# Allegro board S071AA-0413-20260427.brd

Outline 292.64 x 429.26 mm; copper layers: TOP, L02_DGND, L03_DIG, L04_DGND, L05_DIG, L06_DGND, L07_DIG, L08_DGND, L09_DPS, L10_DGND, L11_DPS, L12_DGND, L13_CBIT, L14_5V, L15_DGND, L16_DPS, L17_DGND, L18_DIG, L19_DGND, L20_DIG, L21_DGND, L22_DIG, L23_DGND, L24_DIG, L25_DGND, BOTTOM. Coordinates in mm from the lower left corner of the outline.

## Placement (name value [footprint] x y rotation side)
BDB4  BD120-3A-S8  [FB0805]  17.8 140.46 180 bottom
BDB5  BD120-3A-S8  [FB0805]  142.51 263.88 180 bottom
BDB6  BD120-3A-S8  [FB0805]  175.3 247.77 180 bottom
BDB7  BD120-3A-S8  [FB0805]  192.18 233.42 180 bottom
BDB8  BD120-3A-S8  [FB0805]  189.46 211.4 180 bottom
BDB9  BD120-3A-S8  [FB0805]  188.62 176.29 180 bottom
BDB10  BD120-3A-S8  [FB0805]  162.21 175.22 180 bottom
BDB13  BD120-3A-S8  [FB0805]  63.77 269.13 180 bottom
BDB14  BD120-3A-S8  [FB0805]  60.72 250.95 180 bottom
BDB15  BD120-3A-S8  [FB0805]  63.77 266.34 180 bottom
BDB16  BD120-3A-S8  [FB0805]  60.72 248.16 180 bottom
BDB17  BD120-3A-S8  [FB0805]  162.21 172.43 180 bottom
BDB18  BD120-3A-S8  [FB0805]  188.62 179.08 180 bottom
BDB19  BD120-3A-S8  [FB0805]  276.88 285.24 180 bottom
BDB20  BD120-3A-S8  [FB0805]  278.4 130.3 180 bottom
BDB21  BD120-3A-S8  [FB0805]  278.4 133.1 180 bottom
BDB22  BD120-3A-S8  [FB0805]  107.34 283.04 180 bottom
BDB23  BD120-3A-S8  [FB0805]  107.34 285.83 180 bottom
BDB24  BD120-3A-S8  [FB0805]  123.91 255.95 180 bottom
BDB25  BD120-3A-S8  [FB0805]  123.91 258.74 180 bottom
BDB26  BD120-3A-S8  [FB0805]  137.48 248.16 180 bottom
BDB27  BD120-3A-S8  [FB0805]  137.48 245.36 180 bottom
BDB28  BD120-3A-S8  [FB0805]  113.41 271.67 180 bottom
BDB29  BD120-3A-S8  [FB0805]  113.41 268.87 180 bottom
BDB30  BD120-3A-S8  [FB0805]  44.72 271.53 180 bottom
BDB31  BD120-3A-S8  [FB0805]  44.72 274.32 180 bottom
BDB32  BD120-3A-S8  [FB0805]  23.38 216.41 0 bottom
BDB33  BD120-3A-S8  [FB0805]  23.38 219.2 0 bottom
BDB34  BD120-3A-S8  [FB0805]  233.41 270.37 180 bottom
BDB35  BD120-3A-S8  [FB0805]  233.41 267.57 180 bottom
BDB36  BD120-3A-S8  [FB0805]  233.11 210.8 180 bottom
BDB37  BD120-3A-S8  [FB0805]  233.11 208.01 180 bottom
BDB38  BD120-3A-S8  [FB0805]  142.51 266.67 180 bottom
BDB39  BD120-3A-S8  [FB0805]  175.3 250.56 180 bottom
BDB40  BD120-3A-S8  [FB0805]  192.18 236.22 180 bottom
BDB41  BD120-3A-S8  [FB0805]  189.46 214.19 180 bottom
BDB42  BD120-3A-S8  [FB0805]  276.88 282.45 180 bottom
BDB43  BD120-3A-S8  [FB0805]  17.8 143.26 180 bottom
BDB44  BD120-3A-S8  [FB0805]  16.78 284.99 180 bottom
BDB45  BD120-3A-S8  [FB0805]  16.78 282.19 180 bottom
BGA289-12X12-P0.65  REF-CODE-SOCKET  [SOCKET_CODE]  231.41 215.9 0 top
C1  0.01U-16-X7R-S4-YA  [C0402]  178.87 202.62 270 bottom
C2  3.3U-10-X-S4-TDK  [C0402]  176.52 218.6 0 bottom
C3  10U-25-X7R-SA  [C1206]  234.71 279.15 180 bottom
C4  NC/10U-25-X7R-SA  [C1206]  239.79 279.15 0 bottom
C5  22U-16-X-SB  [C1210]  234.2 283.21 180 bottom
C6  NC/47U-16-X5R-SB-MU  [C1210]  240.3 288.29 0 bottom
C7  NC/100U-10-X5R-SB-MU  [C1210]  234.2 288.29 180 bottom
C8  NC/22U-16-X-SB  [C1210]  240.3 283.21 0 bottom
C9  0.1U-16-X-S2-TDK  [C0201]  177.6 202.69 270 bottom
C10  0.1U-16-X-S2-TDK  [C0201]  148.72 210.23 0 bottom
C11  0.1U-16-X-S2-TDK  [C0201]  143.92 210.23 180 bottom
C12  0.1U-16-X-S2-TDK  [C0201]  147.08 211.84 180 bottom
C13  0.1U-16-X-S2-TDK  [C0201]  145.52 210.23 0 bottom
C14  0.1U-16-X-S2-TDK  [C0201]  147.12 212.63 180 bottom
C15  0.1U-16-X-S2-TDK  [C0201]  145.45 211.84 0 bottom
C16  0.1U-16-X-S2-TDK  [C0201]  145.52 212.63 0 bottom
C17  0.1U-16-X-S2-TDK  [C0201]  142.32 210.23 0 bottom
C18  0.1U-16-X-S2-TDK  [C0201]  141.92 211.43 90 bottom
C19  0.1U-16-X-S2-TDK  [C0201]  148.32 213.83 90 bottom
C20  0.1U-16-X-S2-TDK  [C0201]  155.61 211.84 0 bottom
C21  0.1U-16-X-S2-TDK  [C0201]  141.92 215.43 90 bottom
C22  0.1U-16-X-S2-TDK  [C0201]  155.61 212.6 0 bottom
C23  0.1U-16-X-S2-TDK  [C0201]  155.61 213.36 0 bottom
C24  0.1U-16-X-S2-TDK  [C0201]  155.61 211.07 0 bottom
C25  0.1U-16-X-S2-TDK  [C0201]  150.32 211.03 180 bottom
C26  0.1U-16-X-S2-TDK  [C0201]  150.32 212.63 180 bottom
C27  0.1U-16-X-S2-TDK  [C0201]  150.32 210.23 180 bottom
C28  0.1U-16-X-S2-TDK  [C0201]  147.12 210.23 180 bottom
C29  0.1U-16-X-S2-TDK  [C0201]  150.32 211.83 180 bottom
C30  0.1U-16-X-S2-TDK  [C0201]  141.92 213.83 270 bottom
C31  0.1U-16-X-S2-TDK  [C0201]  141.92 217.03 270 bottom
C32  0.1U-16-X-S2-TDK  [C0201]  149.52 219.03 180 bottom
C33  0.1U-16-X-S2-TDK  [C0201]  141.92 218.63 90 bottom
C34  0.1U-16-X-S2-TDK  [C0201]  150.72 218.63 270 bottom
C35  0.1U-16-X-S2-TDK  [C0201]  147.92 219.03 0 bottom
C36  0.1U-16-X-S2-TDK  [C0201]  144.72 219.03 0 bottom
C37  0.1U-16-X-S2-TDK  [C0201]  143.12 219.03 180 bottom
C38  0.1U-16-X-S2-TDK  [C0201]  144.32 215.43 270 bottom
C39  0.1U-16-X-S2-TDK  [C0201]  147.52 213.83 90 bottom
C40  0.1U-16-X-S2-TDK  [C0201]  143.92 212.63 180 bottom
C41  0.1U-16-X-S2-TDK  [C0201]  145.12 213.83 90 bottom
C42  0.1U-16-X-S2-TDK  [C0201]  144.32 213.83 90 bottom
C43  0.1U-16-X-S2-TDK  [C0201]  143.92 216.63 180 bottom
C44  0.1U-16-X-S2-TDK  [C0201]  148.32 215.43 270 bottom
C45  0.1U-16-X-S2-TDK  [C0201]  148.72 216.63 0 bottom
C46  0.1U-16-X-S2-TDK  [C0201]  147.12 215.83 180 bottom
C47  0.1U-16-X-S2-TDK  [C0201]  147.12 216.63 180 bottom
C48  0.1U-16-X-S2-TDK  [C0201]  145.52 215.83 0 bottom
C49  0.1U-16-X-S2-TDK  [C0201]  145.52 216.63 0 bottom
C50  10U-25-X7R-SA  [C1206]  128.03 279.15 0 bottom
C51  NC/10U-25-X7R-SA  [C1206]  122.95 279.15 180 bottom
C52  22U-16-X-SB  [C1210]  128.54 283.21 0 bottom
C53  NC/47U-16-X5R-SB-MU  [C1210]  128.54 288.29 0 bottom
C54  NC/100U-10-X5R-SB-MU  [C1210]  122.44 288.29 180 bottom
C55  NC/22U-16-X-SB  [C1210]  122.44 283.21 180 bottom
C56  10U-25-X7R-SA  [C1206]  150.89 279.15 0 bottom
C57  22U-16-X-SB  [C1210]  151.4 283.21 0 bottom
C58  NC/10U-25-X7R-SA  [C1206]  145.81 279.15 180 bottom
C59  NC/47U-16-X5R-SB-MU  [C1210]  151.4 288.29 0 bottom
C60  NC/100U-10-X5R-SB-MU  [C1210]  145.3 288.29 180 bottom
C61  NC/22U-16-X-SB  [C1210]  145.3 283.21 180 bottom
C62  10U-25-X7R-SA  [C1206]  49.29 279.15 0 bottom
C63  22U-16-X-SB  [C1210]  49.8 283.21 0 bottom
C64  NC/10U-25-X7R-SA  [C1206]  44.21 279.15 180 bottom
C65  NC/47U-16-X5R-SB-MU  [C1210]  49.8 288.29 0 bottom
C66  NC/100U-10-X5R-SB-MU  [C1210]  43.7 288.29 180 bottom
C67  NC/22U-16-X-SB  [C1210]  43.7 283.21 180 bottom
C68  10U-25-X7R-SA  [C1206]  95.01 279.15 180 bottom
C69  22U-16-X-SB  [C1210]  94.5 283.21 180 bottom
C70  NC/10U-25-X7R-SA  [C1206]  100.09 279.15 0 bottom
C71  NC/47U-16-X5R-SB-MU  [C1210]  100.6 288.29 0 bottom
C72  NC/100U-10-X5R-SB-MU  [C1210]  94.5 288.29 180 bottom
C73  NC/22U-16-X-SB  [C1210]  100.6 283.21 0 bottom
C74  10U-25-X7R-SA  [C1206]  176.29 279.15 0 bottom
C75  22U-16-X-SB  [C1210]  176.8 283.21 0 bottom
C76  NC/10U-25-X7R-SA  [C1206]  171.21 279.15 180 bottom
C77  NC/47U-16-X5R-SB-MU  [C1210]  176.8 288.29 0 bottom
C78  NC/100U-10-X5R-SB-MU  [C1210]  170.7 288.29 180 bottom
C79  NC/22U-16-X-SB  [C1210]  170.7 283.21 180 bottom
C80  22U-16-X-SB  [C1210]  207.28 283.21 0 bottom
C81  10U-25-X7R-SA  [C1206]  206.77 279.15 0 bottom
C82  NC/10U-25-X7R-SA  [C1206]  201.69 279.15 180 bottom
C83  NC/47U-16-X5R-SB-MU  [C1210]  207.28 288.29 0 bottom
C84  NC/100U-10-X5R-SB-MU  [C1210]  201.18 288.29 180 bottom
C85  NC/22U-16-X-SB  [C1210]  201.18 283.21 180 bottom
CB1  0.1U-25-X-S6  [C0603]  85.09 132.84 270 bottom
CB2  10U-25-X7R-SA  [C1206]  22.88 297.94 270 bottom
CB3  0.1U-25-X-S6  [C0603]  191.53 134.37 270 bottom
CB4  10U-25-X7R-SA  [C1206]  193.84 133.86 270 bottom
CB5  0.1U-25-X-S6  [C0603]  263.16 289.98 270 bottom
CB6  10U-25-X7R-SA  [C1206]  265.47 289.47 270 bottom
CB7  0.1U-25-X-S6  [C0603]  20.57 298.45 270 bottom
CB8  10U-25-X7R-SA  [C1206]  87.39 132.33 270 bottom
CSDPS225  V93K_CSDPS_DPS32  [PG_VG93K_PF_DPS32_G8D225]  109.49 331.47 0 top
CSDPS226  V93K_CSDPS  [PG_VG93K_PF_DPS32_G8D226]  109.49 351.79 0 top
CSDPS229  V93K_CSDPS_DPS32  [PG_VG93K_PF_DPS32_G8D229]  35.83 331.47 0 top
CSDPS425  V93K_CSDPS_DPS32  [PG_VG93K_PF_DPS32_G8D425]  109.49 341.63 0 top
CSDPS426  V93K_CSDPS  [PG_VG93K_PF_DPS32_G8D426]  109.49 361.95 0 top
CSDPS429  V93K_CSDPS_DPS32  [PG_VG93K_PF_DPS32_G8D429]  35.83 341.63 0 top
D101  V93K_CH  [PG_VG93K_F_G1D101]  183.15 97.79 0 top
D102  V93K_CH  [PG_VG93K_F_G1D102]  183.15 77.47 0 top
D103  V93K_CH  [PG_VG93K_F_G1D103]  183.15 57.15 0 top
D104  V93K_CH  [PG_VG93K_F_G1D104]  183.15 36.83 0 top
D105  V93K_CH  [PG_VG93K_F_G1D105]  256.81 97.79 0 top
D106  V93K_CH  [PG_VG93K_F_G1D106]  256.81 77.47 0 top
D107  V93K_CH  [PG_VG93K_F_G1D107]  256.81 57.15 0 top
D108  V93K_CH  [PG_VG93K_F_G1D108]  256.81 36.83 0 top
D109  V93K_CH  [PG_VG93K_F_G2D109]  256.81 331.47 0 top
D110  V93K_CH  [PG_VG93K_F_G2D110]  256.81 351.79 0 top
D111  V93K_CH  [PG_VG93K_F_G2D111]  256.81 372.11 0 top
D112  V93K_CH  [PG_VG93K_F_G2D112]  256.81 392.43 0 top
D113  V93K_CH  [PG_VG93K_F_G2D113]  183.15 331.47 0 top
D114  V93K_CH  [PG_VG93K_F_G2D114]  183.15 351.79 0 top
D115  V93K_CH  [PG_VG93K_F_G2D115]  183.15 372.11 0 top
D116  V93K_CH  [PG_VG93K_F_G2D116]  183.15 392.43 0 top
D117  V93K_CH  [PG_VG93K_F_G3D117]  35.83 97.79 0 top
D118  V93K_CH  [PG_VG93K_F_G3D118]  35.83 77.47 0 top
D119  V93K_CH  [PG_VG93K_F_G3D119]  35.83 57.15 0 top
D120  V93K_CH  [PG_VG93K_F_G3D120]  35.83 36.83 0 top
D121  V93K_CH  [PG_VG93K_F_G3D121]  109.49 97.79 0 top
D122  V93K_CH  [PG_VG93K_F_G3D122]  109.49 77.47 0 top
D123  V93K_CH  [PG_VG93K_F_G3D123]  109.49 57.15 0 top
D124  V93K_CH  [PG_VG93K_F_G3D124]  109.49 36.83 0 top
D227  V93K_CH  [PG_VG93K_F_G8D227]  109.49 372.11 0 top
D228  V93K_CH  [PG_VG93K_F_G8D228]  109.49 392.43 0 top
D231  V93K_CH  [PG_VG93K_F_G8D231]  35.83 372.11 0 top
D232  V93K_CH  [PG_VG93K_F_G8D232]  35.83 392.43 0 top
D301  V93K_CH  [PG_VG93K_F_PS1600SD_G1_ND]  183.15 87.63 0 top
D302  V93K_CH  [PG_VG93K_F_PS1600SD_G1_ND]  183.15 67.31 0 top
D303  V93K_CH  [PG_VG93K_F_PS1600SD_G1_ND]  183.15 46.99 0 top
D304  V93K_CH  [PG_VG93K_F_PS1600SD_G1_ND]  183.15 26.67 0 top
D305  V93K_CH  [PG_VG93K_F_PS1600SD_G1_ND]  256.81 87.63 0 top
D306  V93K_CH  [PG_VG93K_F_PS1600SD_G1_ND]  256.81 67.31 0 top
D307  V93K_CH  [PG_VG93K_F_PS1600SD_G1_ND]  256.81 46.99 0 top
D308  V93K_CH  [PG_VG93K_F_PS1600SD_G1_ND]  256.81 26.67 0 top
D309  V93K_CH  [PG_VG93K_F_PS1600SD_G2_ND]  256.81 341.63 0 top
D310  V93K_CH  [PG_VG93K_F_PS1600SD_G2_ND]  256.81 361.95 0 top
D311  V93K_CH  [PG_VG93K_F_PS1600SD_G2_ND]  256.81 402.59 0 top
D312  V93K_CH  [PG_VG93K_F_PS1600SD_G2_ND]  256.81 382.27 0 top
D313  V93K_CH  [PG_VG93K_F_PS1600SD_G2_ND]  183.15 341.63 0 top
D314  V93K_CH  [PG_VG93K_F_PS1600SD_G2_ND]  183.15 361.95 0 top
D315  V93K_CH  [PG_VG93K_F_PS1600SD_G2_ND]  183.15 382.27 0 top
D316  V93K_CH  [PG_VG93K_F_PS1600SD_G2_ND]  183.15 402.59 0 top
D317  V93K_CH  [PG_VG93K_F_PS1600SD_G3_ND]  35.83 87.63 0 top
D318  V93K_CH  [PG_VG93K_F_PS1600SD_G3_ND]  35.83 67.31 0 top
D319  V93K_CH  [PG_VG93K_F_PS1600SD_G3_ND]  35.83 46.99 0 top
D320  V93K_CH  [PG_VG93K_F_PS1600SD_G3_ND]  35.83 26.67 0 top
D321  V93K_CH  [PG_VG93K_F_PS1600SD_G3_ND]  109.49 87.63 0 top
D322  V93K_CH  [PG_VG93K_F_PS1600SD_G3_ND]  109.49 67.31 0 top
D323  V93K_CH  [PG_VG93K_F_PS1600SD_G3_ND]  109.49 46.99 0 top
D324  V93K_CH  [PG_VG93K_F_PS1600SD_G3_ND]  109.49 26.67 0 top
D427  V93K_CH  [PG_VG93K_F_G8D427]  109.49 382.27 0 top
D428  V93K_CH  [PG_VG93K_F_G8D428]  109.49 402.59 0 top
D431  V93K_CH  [PG_VG93K_F_G8D431]  35.83 382.27 0 top
D432  V93K_CH  [PG_VG93K_F_G8D432]  35.83 402.59 0 top
DPS1  V93K_DPS  [PG_VG93K_F_G1DPS1]  256.81 16.51 0 top
DPS2  V93K_DPS  [PG_VG93K_F_G2DPS2]  183.15 412.75 0 top
DPS3  V93K_DPS  [PG_VG93K_F_G3DPS3]  109.49 16.51 0 top
DPS8  V93K_DPS  [PG_VG93K_F_G8DPS8]  35.83 412.75 0 top
FD1  FD_040  [FD_040_V2]  18.05 134.62 0 top
FD2  FD_040  [FD_040_V2]  272.05 138.43 0 top
FD3  FD_040  [FD_040_V2]  16.78 292.1 0 top
FD4  FD_040  [FD_040_V2]  277.13 294.64 0 top
FD5  FD_040  [FD_040_V2]  18.05 134.62 180 bottom
FD6  FD_040  [FD_040_V2]  272.05 138.43 180 bottom
FD7  FD_040  [FD_040_V2]  16.78 292.1 180 bottom
FD8  FD_040  [FD_040_V2]  277.13 294.64 180 bottom
FD9  FD_040  [FD_040_V2]  16.78 163.83 0 top
FD10  FD_040  [FD_040_V2]  275.86 265.43 180 bottom
FD11  FD_040  [FD_040_V2]  275.86 163.83 180 bottom
FD12  FD_040  [FD_040_V2]  16.78 163.83 180 bottom
FD13  FD_040  [FD_040_V2]  16.78 265.43 180 bottom
FD14  FD_040  [FD_040_V2]  275.86 163.83 0 top
FD15  FD_040  [FD_040_V2]  16.78 265.43 0 top
FD16  FD_040  [FD_040_V2]  275.86 265.43 0 top
FSS0AS071A  REF-CODE-CHIP  [CHIP_CODE]  231.41 213.36 0 top
H1  M3-HOLE  [M3_NPTH169]  277.13 185.42 0 top
H2  M3-HOLE  [M3_NPTH169]  18.05 246.38 0 top
H3  M3-HOLE  [M3_NPTH169]  18.05 185.42 0 top
H4  M3-HOLE  [M3_NPTH169]  275.86 242.57 0 top
JG-250905AA011  REF-CODE-SOCKET  [SOCKET_CODE]  231.16 208.03 0 top
K1  2911-05-321-A-V2  [RL_COTO2911_5V_RLPIN]  99.58 186.94 0 bottom
K2  2911-05-321-A-V2  [RL_COTO2911_5V_RLPIN]  75.96 186.94 0 bottom
K3  2911-05-321-A-V2  [RL_COTO2911_5V_RLPIN]  52.34 186.94 0 bottom
K4  2911-05-321-A-V2  [RL_COTO2911_5V_RLPIN]  28.72 209.8 0 bottom
K5  2911-05-321-A-V2  [RL_COTO2911_5V_RLPIN]  28.72 202.18 0 bottom
K6  2911-05-321-A-V2  [RL_COTO2911_5V_RLPIN]  28.72 194.56 0 bottom
K7  2911-05-321-A-V2  [RL_COTO2911_5V_RLPIN]  52.34 209.8 0 bottom
K8  2911-05-321-A-V2  [RL_COTO2911_5V_RLPIN]  52.34 202.18 0 bottom
K9  2911-05-321-A-V2  [RL_COTO2911_5V_RLPIN]  52.34 194.56 0 bottom
K10  2911-05-321-A-V2  [RL_COTO2911_5V_RLPIN]  75.96 194.56 0 bottom
K11  2911-05-321-A-V2  [RL_COTO2911_5V_RLPIN]  99.58 194.56 0 bottom
K12  2911-05-321-A-V2  [RL_COTO2911_5V_RLPIN]  75.96 202.18 0 bottom
K13  2911-05-321-A-V2  [RL_COTO2911_5V_RLPIN]  99.58 202.18 0 bottom
K14  2911-05-321-A-V2  [RL_COTO2911_5V_RLPIN]  75.96 209.8 0 bottom
K15  2911-05-321-A-V2  [RL_COTO2911_5V_RLPIN]  99.58 209.8 0 bottom
K16  2911-05-321-A-V2  [RL_COTO2911_5V_RLPIN]  28.72 186.94 0 bottom
K17  2911-05-321-A-V2  [RL_COTO2911_5V_RLPIN]  28.72 217.42 0 bottom
K18  2911-05-321-A-V2  [RL_COTO2911_5V_RLPIN]  52.34 217.42 0 bottom
K19  2911-05-321-A-V2  [RL_COTO2911_5V_RLPIN]  75.96 217.42 0 bottom
K20  2911-05-321-A-V2  [RL_COTO2911_5V_RLPIN]  99.58 217.42 0 bottom
K21  2911-05-321-A-V2  [RL_COTO2911_5V_RLPIN]  28.72 225.04 0 bottom
K22  2911-05-321-A-V2  [RL_COTO2911_5V_RLPIN]  52.34 225.04 0 bottom
K23  2911-05-321-A-V2  [RL_COTO2911_5V_RLPIN]  75.96 225.04 0 bottom
K24  2911-05-321-A-V2  [RL_COTO2911_5V_RLPIN]  99.58 225.04 0 bottom
K25  2911-05-321-A-V2  [RL_COTO2911_5V_RLPIN]  28.72 232.66 0 bottom
K26  2911-05-321-A-V2  [RL_COTO2911_5V_RLPIN]  52.34 232.66 0 bottom
K27  2911-05-321-A-V2  [RL_COTO2911_5V_RLPIN]  75.96 232.66 0 bottom
K28  2911-05-321-A-V2  [RL_COTO2911_5V_RLPIN]  99.58 232.66 0 bottom
K29  2911-05-321-A-V2  [RL_COTO2911_5V_RLPIN]  28.72 240.28 0 bottom
K30  2911-05-321-A-V2  [RL_COTO2911_5V_RLPIN]  52.34 240.28 0 bottom
K31  2911-05-321-A-V2  [RL_COTO2911_5V_RLPIN]  75.96 240.28 0 bottom
K32  2911-05-321-A-V2  [RL_COTO2911_5V_RLPIN]  99.58 240.28 0 bottom
K33  2911-05-321-A-V2  [RL_COTO2911_5V_RLPIN]  115.59 161.8 90 bottom
K34  2911-05-321-A-V2  [RL_COTO2911_5V_RLPIN]  138.45 161.8 90 bottom
K35  2911-05-321-A-V2  [RL_COTO2911_5V_RLPIN]  115.59 138.68 90 bottom
K36  2911-05-321-A-V2  [RL_COTO2911_5V_RLPIN]  138.45 138.43 90 bottom
K37  2911-05-321-A-V2  [RL_COTO2911_5V_RLPIN]  123.21 161.8 90 bottom
K38  2911-05-321-A-V2  [RL_COTO2911_5V_RLPIN]  146.07 161.8 90 bottom
K39  2911-05-321-A-V2  [RL_COTO2911_5V_RLPIN]  123.21 138.68 90 bottom
K40  2911-05-321-A-V2  [RL_COTO2911_5V_RLPIN]  146.07 138.43 90 bottom
K41  2911-05-321-A-V2  [RL_COTO2911_5V_RLPIN]  130.83 161.8 90 bottom
K42  2911-05-321-A-V2  [RL_COTO2911_5V_RLPIN]  153.69 161.8 90 bottom
K43  2911-05-321-A-V2  [RL_COTO2911_5V_RLPIN]  130.83 138.68 90 bottom
K44  2911-05-321-A-V2  [RL_COTO2911_5V_RLPIN]  153.69 138.43 90 bottom
K45  UA2-5NJ-A-V3  [RL_NECUA2_5V_V3]  177.82 207.52 0 bottom
K46  UA2-5NJ-A-V3  [RL_NECUA2_5V_V3]  177.82 214.63 0 bottom
KB1-2  TP03-D  [TP_060_040]  32.53 133.86 0 top
KB1-3  TP03-D  [TP_060_040]  32.02 137.92 0 top
KB1-4  TP03-D  [TP_060_040]  34.56 141.48 0 top
KB1-6  TP03-D  [TP_060_040]  41.67 141.48 0 top
KB1-7  TP03-D  [TP_060_040]  44.21 137.92 0 top
KB1-8  TP03-D  [TP_060_040]  43.7 133.86 0 top
KB2-2  TP03-D  [TP_060_040]  50.82 133.86 0 top
KB2-3  TP03-D  [TP_060_040]  50.31 137.92 0 top
KB2-4  TP03-D  [TP_060_040]  52.85 141.48 0 top
KB2-6  TP03-D  [TP_060_040]  59.96 141.48 0 top
KB2-7  TP03-D  [TP_060_040]  62.5 137.92 0 top
KB2-8  TP03-D  [TP_060_040]  61.99 133.86 0 top
KB3-4  TP03-D  [TP_060_040]  59.45 151.64 0 top
KB3-5  TP03-D  [TP_060_040]  59.45 149.1 0 top
KB3-8  TP03-D  [TP_060_040]  34.56 149.1 0 top
KB4-4  TP03-D  [TP_060_040]  59.45 159.26 0 top
KB4-5  TP03-D  [TP_060_040]  59.45 156.72 0 top
KB4-8  TP03-D  [TP_060_040]  34.56 156.72 0 top
KS1  NC/712D-5-V2  [RL_712D_5V_V2]  38.12 136.4 180 bottom
KS2  NC/712D-5-V2  [RL_712D_5V_V2]  56.4 136.4 180 bottom
KS3  NC/2911-05-321-A  [RL_COTO2911_5V_RLPIN]  55.9 151.64 180 bottom
KS4  NC/2911-05-321-A  [RL_COTO2911_5V_RLPIN]  55.9 159.26 180 bottom
LD1  LDG-2-S6  [LED_0603]  111.01 184.4 180 top
LD2  LDG-2-S6  [LED_0603]  87.39 184.4 180 top
LD3  LDG-2-S6  [LED_0603]  63.77 184.4 180 top
LD4  LDG-2-S6  [LED_0603]  40.15 207.26 180 top
LD5  LDG-2-S6  [LED_0603]  40.15 199.64 180 top
LD6  LDG-2-S6  [LED_0603]  40.15 192.02 180 top
LD7  LDG-2-S6  [LED_0603]  63.77 207.26 180 top
LD8  LDG-2-S6  [LED_0603]  63.77 199.64 180 top
LD9  LDG-2-S6  [LED_0603]  63.77 192.02 180 top
LD10  LDG-2-S6  [LED_0603]  87.39 192.02 180 top
LD11  LDG-2-S6  [LED_0603]  111.01 192.02 180 top
LD12  LDG-2-S6  [LED_0603]  87.39 199.64 180 top
LD13  LDG-2-S6  [LED_0603]  111.01 199.64 180 top
LD14  LDG-2-S6  [LED_0603]  87.39 207.26 180 top
LD15  LDG-2-S6  [LED_0603]  111.01 207.26 180 top
LD16  LDG-2-S6  [LED_0603]  40.15 184.4 180 top
LD17  LDG-2-S6  [LED_0603]  40.15 214.88 180 top
LD18  LDG-2-S6  [LED_0603]  63.77 214.88 180 top
LD19  LDG-2-S6  [LED_0603]  87.39 214.88 180 top
LD20  LDG-2-S6  [LED_0603]  111.01 214.88 180 top
LD21  LDG-2-S6  [LED_0603]  40.15 222.5 180 top
LD22  LDG-2-S6  [LED_0603]  63.77 222.5 180 top
LD23  LDG-2-S6  [LED_0603]  87.39 222.5 180 top
LD24  LDG-2-S6  [LED_0603]  111.01 222.5 180 top
LD25  LDG-2-S6  [LED_0603]  40.15 230.12 180 top
LD26  LDG-2-S6  [LED_0603]  63.77 230.12 180 top
LD27  LDG-2-S6  [LED_0603]  87.39 230.12 180 top
LD28  LDG-2-S6  [LED_0603]  111.01 230.12 180 top
LD29  LDG-2-S6  [LED_0603]  40.15 237.74 180 top
LD30  LDG-2-S6  [LED_0603]  63.77 237.74 180 top
LD31  LDG-2-S6  [LED_0603]  87.39 237.74 180 top
LD32  LDG-2-S6  [LED_0603]  111.01 237.74 180 top
LD33  LDG-2-S6  [LED_0603]  118.13 173.23 270 top
LD34  LDG-2-S6  [LED_0603]  140.99 173.23 270 top
LD35  LDG-2-S6  [LED_0603]  118.13 150.11 270 top
LD36  LDG-2-S6  [LED_0603]  140.99 149.86 270 top
LD37  LDG-2-S6  [LED_0603]  125.75 173.23 270 top
LD38  LDG-2-S6  [LED_0603]  148.61 173.23 270 top
LD39  LDG-2-S6  [LED_0603]  125.75 150.11 270 top
LD40  LDG-2-S6  [LED_0603]  148.61 149.86 270 top
LD41  LDG-2-S6  [LED_0603]  133.37 173.23 270 top
LD42  LDG-2-S6  [LED_0603]  156.23 173.23 270 top
LD43  LDG-2-S6  [LED_0603]  133.37 150.11 270 top
LD44  LDG-2-S6  [LED_0603]  156.23 149.86 270 top
LD45  LDG-2-S6  [LED_0603]  184.17 209.04 270 top
LD46  LDG-2-S6  [LED_0603]  184.13 215.81 270 top
LDB1  LDG-2-S8  [LED_0805]  96.54 131.83 270 top
LDB2  LDG-2-S6  [LED_0603]  39.13 130.81 180 top
LDB3  LDG-2-S6  [LED_0603]  57.42 130.81 180 top
LDB4  LDG-2-S6  [LED_0603]  44.21 154.18 0 top
LDB5  LDG-2-S6  [LED_0603]  44.21 161.8 0 top
LOGO1  -  [LOGO_KT_KSMT]  228.36 223.52 0 top
LOGO2  LOGO_FY_Faraday  [LOGO_FY_FARADAY]  223.54 158.75 0 top
LRB1  330-1-S6  [R0603]  94 131.83 90 top
LRB2  470-1-S4  [R0402_UNBGA_V2]  36.59 130.81 0 top
LRB3  470-1-S4  [R0402_UNBGA_V2]  54.88 130.81 0 top
LRB4  470-1-S4  [R0402_UNBGA_V2]  48.28 154.18 180 top
LRB5  470-1-S4  [R0402_UNBGA_V2]  48.28 161.8 180 top
M5  V93K-TOUCHSENSOR-FY  [V93K_TOUCHSENSOR_FY]  146.32 214.63 0 top
NOREF  -  []  86.64 199.64 0 top
NOREF#2  -  []  54.09 130.42 90 top
NOREF#3  -  []  142.76 286.26 90 top
NOREF#4  -  []  38.75 221.85 90 top
NOREF#5  -  []  86.54 206.81 90 top
NOREF#6  -  []  146.52 209.91 90 top
NOREF#7  -  []  131.08 286.26 90 top
NOREF#8  -  []  38.38 130.81 0 top
NOREF#9  -  []  63.02 184.4 0 top
NOREF#10  -  []  149.72 209.91 90 top
NOREF#11  -  []  35.8 130.42 90 top
NOREF#12  -  []  181.42 205.92 0 top
NOREF#13  -  []  42.18 283.21 0 top
NOREF#14  -  []  205.76 288.29 0 top
NOREF#15  -  []  86.54 191.57 0 top
NOREF#16  -  []  127.02 283.21 0 top
NOREF#17  -  []  145.22 212.63 0 top
NOREF#18  -  []  36.17 130.81 0 top
NOREF#19  -  []  169.18 288.29 0 top
NOREF#20  -  []  143.32 210.55 0 top
NOREF#21  -  []  132.72 148.71 0 top
NOREF#22  -  []  63.02 192.02 0 top
NOREF#23  -  []  110.16 222.05 0 top
NOREF#24  -  []  39.4 214.88 0 top
NOREF#25  -  []  177.28 202.09 0 top
NOREF#26  -  []  239.03 30.48 0 top
NOREF#27  -  []  173.82 201.42 90 top
NOREF#28  -  []  142.76 290.32 0 top
NOREF#29  -  []  138.72 221.43 90 top
NOREF#30  -  []  277.13 25.4 90 top
NOREF#31  -  []  173.82 216.23 0 top
NOREF#32  -  []  142.76 285.24 0 top
NOREF#33  -  []  39.3 237.29 90 top
NOREF#34  -  []  38.75 229.47 90 top
NOREF#35  -  []  144 214.43 0 top
NOREF#36  -  []  146.52 212.95 0 top
NOREF#37  -  []  62.92 214.43 0 top
NOREF#38  -  []  174.32 203.47 0 top
NOREF#39  -  []  148.64 213.23 90 top
NOREF#40  -  []  110.16 206.81 90 top
NOREF#41  -  []  98.06 286.26 0 top
NOREF#42  -  []  179.34 281.18 90 top
NOREF#43  -  []  162.83 27.94 0 top
NOREF#44  -  []  62.37 191.37 90 top
NOREF#45  -  []  62.37 183.75 90 top
NOREF#46  -  []  37.73 130.16 90 top
NOREF#47  -  []  155.01 211.52 0 top
NOREF#48  -  []  147.96 171.83 0 top
NOREF#49  -  []  142.02 210.23 0 top
NOREF#50  -  []  142.82 219.03 0 top
NOREF#51  -  []  109.61 221.85 90 top
NOREF#52  -  []  39.3 222.05 0 top
NOREF#53  -  []  125.75 172.48 90 top
NOREF#54  -  []  143.32 216.95 0 top
NOREF#55  -  []  133.82 172.38 90 top
NOREF#56  -  []  145.12 213.53 90 top
NOREF#57  -  []  62.92 237.29 0 top
NOREF#58  -  []  138.72 222.23 0 top
NOREF#59  -  []  156.21 210.75 90 top
NOREF#60  -  []  110.16 191.57 90 top
NOREF#61  -  []  110.16 222.05 90 top
NOREF#62  -  []  199.66 283.21 0 top
NOREF#63  -  []  174.32 200.97 90 top
NOREF#64  -  []  155.31 211.07 0 top
NOREF#65  -  []  39.3 183.95 0 top
NOREF#66  -  []  286.62 112.62 90 top
NOREF#67  -  []  184.62 208.19 90 top
NOREF#68  -  []  141.92 215.13 90 top
NOREF#69  -  []  86.54 206.81 0 top
NOREF#70  -  []  39.3 206.81 0 top
NOREF#71  -  []  39.3 191.57 0 top
NOREF#72  -  []  138.72 207.03 90 top
NOREF#73  -  []  39.3 229.67 90 top
NOREF#74  -  []  62.37 229.47 90 top
NOREF#75  -  []  146.52 216.15 0 top
NOREF#76  -  []  29.05 298.96 0 top
NOREF#77  -  []  49.07 153.79 90 top
NOREF#78  -  []  118.58 149.26 90 top
NOREF#79  -  []  143.78 283.21 0 top
NOREF#80  -  []  110.16 206.81 0 top
NOREF#81  -  []  54.45 130.81 0 top
NOREF#82  -  []  38.28 130.36 90 top
NOREF#83  -  []  85.99 198.99 90 top
NOREF#84  -  []  95.54 130.03 0 top
NOREF#85  -  []  38.75 214.23 90 top
NOREF#86  -  []  286.62 16.51 90 top
NOREF#87  -  []  150.02 212.63 0 top
NOREF#88  -  []  56.67 130.81 0 top
NOREF#89  -  []  117.68 172.38 0 top
NOREF#90  -  []  91.96 286.26 90 top
NOREF#91  -  []  142.76 281.18 90 top
NOREF#92  -  []  47.26 281.18 0 top
NOREF#93  -  []  134.32 202.63 90 top
NOREF#94  -  []  203.47 66.04 90 top
NOREF#95  -  []  39.3 191.57 90 top
NOREF#96  -  []  45.61 153.53 90 top
NOREF#97  -  []  141.44 149.01 90 top
NOREF#98  -  []  146.52 215.51 90 top
NOREF#99  -  []  304.32 293.63 0 top
NOREF#100  -  []  47.49 153.79 0 top
NOREF#101  -  []  63.02 207.26 0 top
NOREF#102  -  []  162.83 68.58 0 top
NOREF#103  -  []  143.32 212.31 90 top
NOREF#104  -  []  -23.68 135.63 0 top
NOREF#105  -  []  119.9 285.24 0 top
NOREF#106  -  []  176.02 216.23 0 top
NOREF#107  -  []  91.96 290.32 0 top
NOREF#108  -  []  119.9 290.32 0 top
NOREF#109  -  []  155.58 148.46 0 top
NOREF#110  -  []  86.64 192.02 0 top
NOREF#111  -  []  62.92 206.81 90 top
NOREF#112  -  []  45.06 153.73 90 top
NOREF#113  -  []  110.26 222.5 0 top
NOREF#114  -  []  145.15 211.84 0 top
NOREF#115  -  []  43.36 162.25 0 top
NOREF#116  -  []  146.82 210.23 0 top
NOREF#117  -  []  92.98 288.29 0 top
NOREF#118  -  []  143.32 212.95 0 top
NOREF#119  -  []  150.02 211.83 0 top
NOREF#120  -  []  141.92 213.53 90 top
NOREF#121  -  []  168.16 285.24 0 top
NOREF#122  -  []  231.66 290.32 0 top
NOREF#123  -  []  39.4 207.26 0 top
NOREF#124  -  []  173.82 209.12 0 top
NOREF#125  -  []  155.01 212.28 0 top
NOREF#126  -  []  153.94 281.18 90 top
NOREF#127  -  []  86.54 199.19 0 top
NOREF#128  -  []  143.62 212.63 0 top
NOREF#129  -  []  38.28 130.36 0 top
NOREF#130  -  []  168.16 290.32 0 top
NOREF#131  -  []  41.16 281.18 90 top
NOREF#132  -  []  168.16 286.26 90 top
NOREF#133  -  []  110.16 229.67 90 top
NOREF#134  -  []  38.75 191.37 90 top
NOREF#135  -  []  62.92 199.19 0 top
NOREF#136  -  []  120.92 288.29 0 top
NOREF#137  -  []  141.72 209.91 0 top
NOREF#138  -  []  141.44 172.38 90 top
NOREF#139  -  []  172.17 211.63 0 top
NOREF#140  -  []  141.92 218.33 90 top
NOREF#141  -  []  236.49 48.26 0 top
NOREF#142  -  []  142.24 210.83 90 top
NOREF#143  -  []  144.8 214.43 0 top
NOREF#144  -  []  181.42 213.03 90 top
NOREF#145  -  []  140.34 171.83 0 top
NOREF#146  -  []  84.64 133.69 0 top
NOREF#147  -  []  232.68 288.29 0 top
NOREF#148  -  []  148.61 149.11 90 top
NOREF#149  -  []  45.06 161.35 90 top
NOREF#150  -  []  121.32 239.63 90 top
NOREF#151  -  []  175.28 283.21 0 top
NOREF#152  -  []  133.37 172.48 90 top
NOREF#153  -  []  119.9 286.26 90 top
NOREF#154  -  []  38.75 198.99 90 top
NOREF#155  -  []  173.82 216.23 0 top
NOREF#156  -  []  86.54 237.29 90 top
NOREF#157  -  []  109.61 237.09 90 top
NOREF#158  -  []  178.22 216.23 0 top
NOREF#159  -  []  110.16 191.57 0 top
NOREF#160  -  []  47.85 154.18 0 top
NOREF#161  -  []  98.06 281.18 0 top
NOREF#162  -  []  146.12 212.31 90 top
NOREF#163  -  []  62.37 221.85 90 top
NOREF#164  -  []  148.32 215.13 90 top
NOREF#165  -  []  121.32 189.63 90 top
NOREF#166  -  []  109.61 214.23 90 top
NOREF#167  -  []  146.82 216.63 0 top
NOREF#168  -  []  62.92 229.67 0 top
NOREF#169  -  []  149.72 210.55 0 top
NOREF#170  -  []  231.66 285.24 0 top
NOREF#171  -  []  142.52 218.71 90 top
NOREF#172  -  []  153.94 286.26 90 top
NOREF#173  -  []  165.37 50.8 0 top
NOREF#174  -  []  204.74 286.26 0 top
NOREF#175  -  []  141.6 216.43 90 top
NOREF#176  -  []  85.99 206.61 90 top
NOREF#177  -  []  86.64 207.26 0 top
NOREF#178  -  []  86.54 199.19 90 top
NOREF#179  -  []  38.75 206.61 90 top
NOREF#180  -  []  172.17 204.52 0 top
NOREF#181  -  []  184.13 215.06 90 top
NOREF#182  -  []  141.92 211.13 90 top
NOREF#183  -  []  110.16 229.67 0 top
NOREF#184  -  []  147.84 213.23 90 top
NOREF#185  -  []  63.02 230.12 0 top
NOREF#186  -  []  47.26 286.26 0 top
NOREF#187  -  []  103.14 281.18 90 top
NOREF#188  -  []  85.99 229.47 90 top
NOREF#189  -  []  63.02 237.74 0 top
NOREF#190  -  []  144.64 213.23 90 top
NOREF#191  -  []  56.57 130.36 0 top
NOREF#192  -  []  148.32 213.53 90 top
NOREF#193  -  []  148.61 172.48 90 top
NOREF#194  -  []  141.92 216.73 90 top
NOREF#195  -  []  134.32 226.63 0 top
NOREF#196  -  []  239.03 91.44 0 top
NOREF#197  -  []  149.72 211.51 90 top
NOREF#198  -  []  86.64 237.74 0 top
NOREF#199  -  []  146.82 212.63 0 top
NOREF#200  -  []  147.62 219.03 0 top
NOREF#201  -  []  172.17 204.52 0 top
NOREF#202  -  []  39.4 199.64 0 top
NOREF#203  -  []  125.32 193.63 90 top
NOREF#204  -  []  48.28 283.21 0 top
NOREF#205  -  []  149.88 288.29 0 top
NOREF#206  -  []  91.96 285.24 0 top
NOREF#207  -  []  86.54 237.29 0 top
NOREF#208  -  []  38.75 183.75 90 top
NOREF#209  -  []  149.88 283.21 0 top
NOREF#210  -  []  146.78 211.84 0 top
NOREF#211  -  []  110.26 199.64 0 top
NOREF#212  -  []  85.99 221.85 90 top
NOREF#213  -  []  62.37 214.23 90 top
NOREF#214  -  []  236.49 68.58 0 top
NOREF#215  -  []  236.49 88.9 0 top
NOREF#216  -  []  39.3 214.43 0 top
NOREF#217  -  []  156.21 211.52 90 top
NOREF#218  -  []  175.28 288.29 0 top
NOREF#219  -  []  39.3 229.67 0 top
NOREF#220  -  []  86.54 222.05 90 top
NOREF#221  -  []  144.12 218.71 0 top
NOREF#222  -  []  183.07 211.63 90 top
NOREF#223  -  []  110.16 214.43 0 top
NOREF#224  -  []  119.9 281.18 90 top
NOREF#225  -  []  62.92 214.43 90 top
NOREF#226  -  []  146.52 212.31 90 top
NOREF#227  -  []  121.32 244.63 0 top
NOREF#228  -  []  -23.68 125.63 90 top
NOREF#229  -  []  143.32 209.91 90 top
NOREF#230  -  []  231.66 281.18 90 top
NOREF#231  -  []  156.23 172.48 90 top
NOREF#232  -  []  110.26 237.74 0 top
NOREF#233  -  []  121.32 186.63 90 top
NOREF#234  -  []  145.22 215.83 0 top
NOREF#235  -  []  39.4 192.02 0 top
NOREF#236  -  []  148.92 219.35 0 top
NOREF#237  -  []  150.4 218.03 0 top
NOREF#238  -  []  147.96 148.46 0 top
NOREF#239  -  []  149.32 209.91 90 top
NOREF#240  -  []  140.54 149.01 0 top
NOREF#241  -  []  38.75 237.09 90 top
NOREF#242  -  []  86.54 222.05 0 top
NOREF#243  -  []  63.02 222.5 0 top
NOREF#244  -  []  156.21 212.28 90 top
NOREF#245  -  []  142.52 219.35 0 top
NOREF#246  -  []  144 214.83 0 top
NOREF#247  -  []  140.99 172.48 90 top
NOREF#248  -  []  262.71 290.83 0 top
NOREF#249  -  []  150.72 218.33 90 top
NOREF#250  -  []  109.61 198.99 90 top
NOREF#251  -  []  49.07 161.41 90 top
NOREF#252  -  []  62.92 183.95 0 top
NOREF#253  -  []  62.92 191.57 90 top
NOREF#254  -  []  165.37 71.12 0 top
NOREF#255  -  []  149.06 149.01 90 top
NOREF#256  -  []  125.1 171.83 0 top
NOREF#257  -  []  199.66 288.29 0 top
NOREF#258  -  []  156.23 149.11 90 top
NOREF#259  -  []  172.17 211.63 0 top
NOREF#260  -  []  146.52 210.55 0 top
NOREF#261  -  []  120.92 283.21 0 top
NOREF#262  -  []  148.92 218.71 90 top
NOREF#263  -  []  109.61 183.75 90 top
NOREF#264  -  []  117.68 149.26 0 top
NOREF#265  -  []  43.46 154.18 0 top
NOREF#266  -  []  173.82 203.02 0 top
NOREF#267  -  []  149.72 211.35 0 top
NOREF#268  -  []  52.34 281.18 90 top
NOREF#269  -  []  126.2 149.26 90 top
NOREF#270  -  []  125.88 198.79 315 top
NOREF#271  -  []  95.81 130.73 0 top
NOREF#272  -  []  138.72 222.23 0 top
NOREF#273  -  []  144 214.83 90 top
NOREF#274  -  []  110.26 207.26 0 top
NOREF#275  -  []  109.61 229.47 90 top
NOREF#276  -  []  123.32 229.41 0 top
NOREF#277  -  []  20.12 299.3 0 top
NOREF#278  -  []  43.46 161.8 0 top
NOREF#279  -  []  133.37 149.36 90 top
NOREF#280  -  []  42.18 288.29 0 top
NOREF#281  -  []  149.72 212.95 0 top
NOREF#282  -  []  184.58 214.96 90 top
NOREF#283  -  []  110.26 230.12 0 top
NOREF#284  -  []  149.72 210.71 90 top
NOREF#285  -  []  125.1 148.71 0 top
NOREF#286  -  []  140.99 149.11 90 top
NOREF#287  -  []  155.78 149.01 0 top
NOREF#288  -  []  149.32 216.31 90 top
NOREF#289  -  []  62.92 222.05 90 top
NOREF#290  -  []  183.72 208.19 0 top
NOREF#291  -  []  142.24 218.03 90 top
NOREF#292  -  []  155.31 211.84 0 top
NOREF#293  -  []  155.78 172.38 0 top
NOREF#294  -  []  141.6 213.23 0 top
NOREF#295  -  []  144.92 215.51 0 top
NOREF#296  -  []  148.42 210.23 0 top
NOREF#297  -  []  86.54 214.43 0 top
NOREF#298  -  []  39.4 222.5 0 top
NOREF#299  -  []  237.76 281.18 0 top
NOREF#300  -  []  29.05 297.94 0 top
NOREF#301  -  []  146.48 211.52 90 top
NOREF#302  -  []  97.26 130.73 90 top
NOREF#303  -  []  110.16 214.43 90 top
NOREF#304  -  []  149.22 219.03 0 top
NOREF#305  -  []  142.92 209.91 90 top
NOREF#306  -  []  146.12 209.91 90 top
NOREF#307  -  []  62.37 198.99 90 top
NOREF#308  -  []  130.32 230.63 0 top
NOREF#309  -  []  110.16 199.19 0 top
NOREF#310  -  []  110.26 192.02 0 top
NOREF#311  -  []  148.52 218.71 90 top
NOREF#312  -  []  176.02 209.12 0 top
NOREF#313  -  []  39.4 184.4 0 top
NOREF#314  -  []  118.13 172.48 90 top
NOREF#315  -  []  62.92 199.19 90 top
NOREF#316  -  []  136.32 181.63 90 top
NOREF#317  -  []  144.92 212.31 0 top
NOREF#318  -  []  28.69 297.55 0 top
NOREF#319  -  []  133.82 149.26 90 top
NOREF#320  -  []  97.54 130.03 90 top
NOREF#321  -  []  136.44 199.53 90 top
NOREF#322  -  []  63.02 214.88 0 top
NOREF#323  -  []  198.64 286.26 90 top
NOREF#324  -  []  155.58 171.83 0 top
NOREF#325  -  []  286.62 214.63 90 top
NOREF#326  -  []  41.16 285.24 0 top
NOREF#327  -  []  155.01 210.75 0 top
NOREF#328  -  []  150.4 218.03 90 top
NOREF#329  -  []  183.48 214.41 0 top
NOREF#330  -  []  56.57 130.36 90 top
NOREF#331  -  []  62.92 237.29 90 top
NOREF#332  -  []  91.96 281.18 90 top
NOREF#333  -  []  92.98 283.21 0 top
NOREF#334  -  []  110.16 183.95 90 top
NOREF#335  -  []  181.42 213.03 0 top
NOREF#336  -  []  184.17 208.29 90 top
NOREF#337  -  []  -23.68 303.63 0 top
NOREF#338  -  []  149.72 212.15 0 top
NOREF#339  -  []  132.92 172.38 0 top
NOREF#340  -  []  148.12 209.91 0 top
NOREF#341  -  []  56.02 130.16 90 top
NOREF#342  -  []  144.85 211.52 0 top
NOREF#343  -  []  143.32 216.31 90 top
NOREF#344  -  []  205.76 283.21 0 top
NOREF#345  -  []  145.22 216.63 0 top
NOREF#346  -  []  144.42 219.03 0 top
NOREF#347  -  []  155.31 213.36 0 top
NOREF#348  -  []  126 281.18 0 top
NOREF#349  -  []  118.58 172.38 90 top
NOREF#350  -  []  35.8 131.2 0 top
NOREF#351  -  []  178.22 209.12 0 top
NOREF#352  -  []  41.16 286.26 90 top
NOREF#353  -  []  86.54 191.57 90 top
NOREF#354  -  []  131.22 224.51 0 top
NOREF#355  -  []  277.13 45.72 90 top
NOREF#356  -  []  41.16 290.32 0 top
NOREF#357  -  []  140.54 172.38 0 top
NOREF#358  -  []  86.64 222.5 0 top
NOREF#359  -  []  146.48 212.16 0 top
NOREF#360  -  []  143.78 288.29 0 top
NOREF#361  -  []  146.05 211.52 90 top
NOREF#362  -  []  125.3 149.26 0 top
NOREF#363  -  []  232.68 283.21 0 top
NOREF#364  -  []  39.3 214.43 90 top
NOREF#365  -  []  62.37 237.09 90 top
NOREF#366  -  []  146.52 216.95 0 top
NOREF#367  -  []  28.69 298.57 90 top
NOREF#368  -  []  39.3 222.05 90 top
NOREF#369  -  []  86.54 229.67 90 top
NOREF#370  -  []  28.69 297.55 90 top
NOREF#371  -  []  86.64 184.4 0 top
NOREF#372  -  []  109.61 191.37 90 top
NOREF#373  -  []  238.78 283.21 0 top
NOREF#374  -  []  198.64 290.32 0 top
NOREF#375  -  []  85.99 237.09 90 top
NOREF#376  -  []  86.54 229.67 0 top
NOREF#377  -  []  86.64 230.12 0 top
NOREF#378  -  []  -15.66 125.63 90 top
NOREF#379  -  []  131.54 191.63 90 top
NOREF#380  -  []  47.85 161.8 0 top
NOREF#381  -  []  148.12 216.31 0 top
NOREF#382  -  []  39.4 230.12 0 top
NOREF#383  -  []  173.82 209.12 0 top
NOREF#384  -  []  198.64 285.24 0 top
NOREF#385  -  []  39.3 237.29 0 top
NOREF#386  -  []  179.34 286.26 90 top
NOREF#387  -  []  144.92 216.31 0 top
NOREF#388  -  []  144.32 215.13 90 top
NOREF#389  -  []  277.13 66.04 90 top
NOREF#390  -  []  62.92 206.81 0 top
NOREF#391  -  []  149.72 212.31 90 top
NOREF#392  -  []  191.08 135.22 0 top
NOREF#393  -  []  86.54 214.43 90 top
NOREF#394  -  []  86.54 183.95 90 top
NOREF#395  -  []  203.47 86.36 90 top
NOREF#396  -  []  62.92 229.67 90 top
NOREF#397  -  []  147.32 218.71 0 top
NOREF#398  -  []  148 214.83 0 top
NOREF#399  -  []  142.24 214.83 90 top
NOREF#400  -  []  174.26 286.26 0 top
NOREF#401  -  []  174.26 281.18 0 top
NOREF#402  -  []  148 214.43 0 top
NOREF#403  -  []  127.02 288.29 0 top
NOREF#404  -  []  28.69 298.57 0 top
NOREF#405  -  []  203.47 25.4 90 top
NOREF#406  -  []  39.4 237.74 0 top
NOREF#407  -  []  143.62 216.63 0 top
NOREF#408  -  []  132.92 149.26 0 top
NOREF#409  -  []  85.99 214.23 90 top
NOREF#410  -  []  136.32 181.63 0 top
NOREF#411  -  []  126 286.26 0 top
NOREF#412  -  []  110.16 183.95 0 top
NOREF#413  -  []  126.2 172.38 90 top
NOREF#414  -  []  209.82 286.26 90 top
NOREF#415  -  []  48.28 288.29 0 top
NOREF#416  -  []  168.16 281.18 90 top
NOREF#417  -  []  177.28 202.09 90 top
NOREF#418  -  []  145.32 218.71 90 top
NOREF#419  -  []  165.37 91.44 0 top
NOREF#420  -  []  147.2 214.43 0 top
NOREF#421  -  []  118.13 149.36 90 top
NOREF#422  -  []  156.21 213.04 90 top
NOREF#423  -  []  132.72 171.83 0 top
NOREF#424  -  []  110.16 237.29 0 top
NOREF#425  -  []  99.08 283.21 0 top
NOREF#426  -  []  181.42 205.92 90 top
NOREF#427  -  []  130.32 198.63 90 top
NOREF#428  -  []  183.52 207.64 0 top
NOREF#429  -  []  99.08 288.29 0 top
NOREF#430  -  []  237.76 286.26 0 top
NOREF#431  -  []  45.61 161.15 90 top
NOREF#432  -  []  145.22 210.23 0 top
NOREF#433  -  []  148.42 216.63 0 top
NOREF#434  -  []  52.34 286.26 90 top
NOREF#435  -  []  148.86 281.18 0 top
NOREF#436  -  []  169.18 283.21 0 top
NOREF#437  -  []  277.13 86.36 90 top
NOREF#438  -  []  86.64 214.88 0 top
NOREF#439  -  []  150.02 211.03 0 top
NOREF#440  -  []  43.36 154.63 0 top
NOREF#441  -  []  140.34 148.46 0 top
NOREF#442  -  []  125.3 172.38 0 top
NOREF#443  -  []  162.83 88.9 0 top
NOREF#444  -  []  62.92 191.57 0 top
NOREF#445  -  []  242.84 286.26 90 top
NOREF#446  -  []  125.32 235.63 0 top
NOREF#447  -  []  47.49 161.41 0 top
NOREF#448  -  []  110.26 184.4 0 top
NOREF#449  -  []  165.37 30.48 0 top
NOREF#450  -  []  150.02 210.23 0 top
NOREF#451  -  []  236.49 27.94 0 top
NOREF#452  -  []  103.14 286.26 90 top
NOREF#453  -  []  110.16 199.19 90 top
NOREF#454  -  []  117.48 171.83 0 top
NOREF#455  -  []  183.68 214.96 0 top
NOREF#456  -  []  62.92 183.95 90 top
NOREF#457  -  []  172.82 203.82 0 top
NOREF#458  -  []  183.07 204.52 90 top
NOREF#459  -  []  146.12 215.51 90 top
NOREF#460  -  []  156.68 149.01 90 top
NOREF#461  -  []  242.84 281.18 90 top
NOREF#462  -  []  62.37 206.61 90 top
NOREF#463  -  []  144.32 213.53 90 top
NOREF#464  -  []  148 214.83 90 top
NOREF#465  -  []  148.16 149.01 0 top
NOREF#466  -  []  147.52 213.53 90 top
NOREF#467  -  []  155.01 213.04 0 top
NOREF#468  -  []  110.16 237.29 90 top
NOREF#469  -  []  155.31 212.6 0 top
NOREF#470  -  []  172.82 200.62 90 top
NOREF#471  -  []  148.86 286.26 0 top
NOREF#472  -  []  146.82 215.83 0 top
NOREF#473  -  []  146.12 216.31 90 top
NOREF#474  -  []  54.09 131.2 0 top
NOREF#475  -  []  125.75 149.36 90 top
NOREF#476  -  []  144.92 209.91 0 top
NOREF#477  -  []  63.02 199.64 0 top
NOREF#478  -  []  141.6 216.43 0 top
NOREF#479  -  []  85.99 191.37 90 top
NOREF#480  -  []  239.03 50.8 0 top
NOREF#481  -  []  239.03 71.12 0 top
NOREF#482  -  []  148.16 172.38 0 top
NOREF#483  -  []  204.74 281.18 0 top
NOREF#484  -  []  109.61 206.61 90 top
NOREF#485  -  []  39.3 206.81 90 top
NOREF#486  -  []  110.26 214.88 0 top
NOREF#487  -  []  141.6 219.23 0 top
NOREF#488  -  []  141.6 213.23 90 top
NOREF#489  -  []  141.6 216.03 0 top
NOREF#490  -  []  177.6 202.39 90 top
NOREF#491  -  []  145.44 213.23 90 top
NOREF#492  -  []  198.64 281.18 90 top
NOREF#493  -  []  117.48 148.71 0 top
NOREF#494  -  []  231.66 286.26 90 top
NOREF#495  -  []  156.68 172.38 90 top
NOREF#496  -  []  85.99 183.75 90 top
NOREF#497  -  []  62.92 222.05 0 top
NOREF#498  -  []  39.3 183.95 90 top
NOREF#499  -  []  141.6 212.03 0 top
NOREF#500  -  []  86.54 183.95 0 top
NOREF#501  -  []  316.32 293.63 90 top
NOREF#502  -  []  131.08 281.18 90 top
NOREF#503  -  []  209.82 281.18 90 top
NOREF#504  -  []  143.62 210.23 0 top
NOREF#505  -  []  146.52 216.31 90 top
NOREF#506  -  []  39.3 199.19 90 top
NOREF#507  -  []  149.06 172.38 90 top
NOREF#508  -  []  203.47 45.72 90 top
NOREF#509  -  []  39.3 199.19 0 top
NOREF#510  -  []  162.83 48.26 0 top
NOREF#511  -  []  238.78 288.29 0 top
OSC1  OSC25M-S3225-AKER-3.3V  [OSC_3P2X2P5_4P_AKER]  174.92 202.22 180 bottom
R1  470-1-S4  [R0402]  107.71 184.4 180 top
R2  470-1-S4  [R0402]  84.09 184.4 180 top
R3  470-1-S4  [R0402]  60.47 184.4 180 top
R4  470-1-S4  [R0402]  36.85 207.26 180 top
R5  470-1-S4  [R0402]  36.85 199.64 180 top
R6  470-1-S4  [R0402]  36.85 192.02 180 top
R7  470-1-S4  [R0402]  60.47 207.26 180 top
R8  470-1-S4  [R0402]  60.47 199.64 180 top
R9  470-1-S4  [R0402]  60.47 192.02 180 top
R10  470-1-S4  [R0402]  84.09 192.02 180 top
R11  470-1-S4  [R0402]  107.71 192.02 180 top
R12  470-1-S4  [R0402]  84.09 199.64 180 top
R13  470-1-S4  [R0402]  107.71 199.64 180 top
R14  470-1-S4  [R0402]  84.09 207.26 180 top
R15  470-1-S4  [R0402]  107.71 207.26 180 top
R16  470-1-S4  [R0402]  36.85 184.4 180 top
R17  470-1-S4  [R0402]  36.85 214.88 180 top
R18  470-1-S4  [R0402]  60.47 214.88 180 top
R19  470-1-S4  [R0402]  84.09 214.88 180 top
R20  470-1-S4  [R0402]  107.71 214.88 180 top
R21  470-1-S4  [R0402]  36.85 222.5 180 top
R22  470-1-S4  [R0402]  60.47 222.5 180 top
R23  470-1-S4  [R0402]  84.09 222.5 180 top
R24  470-1-S4  [R0402]  107.71 222.5 180 top
R25  470-1-S4  [R0402]  36.85 230.12 180 top
R26  470-1-S4  [R0402]  60.47 230.12 180 top
R27  470-1-S4  [R0402]  84.09 230.12 180 top
R28  470-1-S4  [R0402]  107.71 230.12 180 top
R29  470-1-S4  [R0402]  36.85 237.74 180 top
R30  470-1-S4  [R0402]  60.47 237.74 180 top
R31  470-1-S4  [R0402]  84.09 237.74 180 top
R32  470-1-S4  [R0402]  107.71 237.74 180 top
R33  470-1-S4  [R0402]  118.13 169.93 270 top
R34  470-1-S4  [R0402]  140.99 169.93 270 top
R35  470-1-S4  [R0402]  118.13 146.81 270 top
R36  470-1-S4  [R0402]  140.99 146.56 270 top
R37  470-1-S4  [R0402]  125.75 169.93 270 top
R38  470-1-S4  [R0402]  148.61 169.93 270 top
R39  470-1-S4  [R0402]  125.75 146.81 270 top
R40  470-1-S4  [R0402]  148.61 146.56 270 top
R41  470-1-S4  [R0402]  133.37 169.93 270 top
R42  470-1-S4  [R0402]  156.23 169.93 270 top
R43  470-1-S4  [R0402]  133.37 146.81 270 top
R44  470-1-S4  [R0402]  156.23 146.56 270 top
R45  470-1-S4  [R0402]  184.17 205.74 270 top
R46  470-1-S4  [R0402]  184.13 213.02 270 top
R123  NC/0-5-S8  [R0805]  232.68 293.37 90 bottom
R124  0-5-S8  [R0805]  230.14 293.37 90 bottom
R125  0-5-SA  [R1206]  235.73 293.37 90 bottom
R126  NC/0-5-SA  [R1206]  238.78 293.37 90 bottom
R127  0-5-S8  [R0805]  227.6 293.37 90 bottom
R128  NC/0-5-S8  [R0805]  225.06 293.37 90 bottom
R129  NC/0-5-S8  [R0805]  120.92 293.37 90 bottom
R130  0-5-S8  [R0805]  118.38 293.37 90 bottom
R131  NC/0-5-SA  [R1206]  123.97 293.37 90 bottom
R132  0-5-SA  [R1206]  127.02 293.37 90 bottom
R133  0-5-S8  [R0805]  115.84 293.37 90 bottom
R134  NC/0-5-S8  [R0805]  113.3 293.37 90 bottom
R135  NC/0-5-S8  [R0805]  143.78 293.37 90 bottom
R136  0-5-S8  [R0805]  141.24 293.37 90 bottom
R137  0-5-SA  [R1206]  149.88 293.37 90 bottom
R138  NC/0-5-SA  [R1206]  146.83 293.37 90 bottom
R139  0-5-S8  [R0805]  138.7 293.37 90 bottom
R140  NC/0-5-S8  [R0805]  136.16 293.37 90 bottom
R141  NC/0-5-S8  [R0805]  42.18 293.37 90 bottom
R142  0-5-S8  [R0805]  39.64 293.37 90 bottom
R143  0-5-SA  [R1206]  48.28 293.37 90 bottom
R144  NC/0-5-SA  [R1206]  45.23 293.37 90 bottom
R145  0-5-S8  [R0805]  37.1 293.37 90 bottom
R146  NC/0-5-S8  [R0805]  34.56 293.37 90 bottom
R147  NC/0-5-S8  [R0805]  92.98 293.37 90 bottom
R148  0-5-S8  [R0805]  90.44 293.37 90 bottom
R149  0-5-SA  [R1206]  99.08 293.37 90 bottom
R150  NC/0-5-SA  [R1206]  96.03 293.37 90 bottom
R151  0-5-S8  [R0805]  87.9 293.37 90 bottom
R152  NC/0-5-S8  [R0805]  85.36 293.37 90 bottom
R153  NC/0-5-S8  [R0805]  169.18 293.37 90 bottom
R154  0-5-S8  [R0805]  166.64 293.37 90 bottom
R155  0-5-SA  [R1206]  172.23 293.37 90 bottom
R156  NC/0-5-SA  [R1206]  175.28 293.37 90 bottom
R157  0-5-S8  [R0805]  164.1 293.37 90 bottom
R158  NC/0-5-S8  [R0805]  161.56 293.37 90 bottom
R159  NC/0-5-S8  [R0805]  199.66 293.37 90 bottom
R160  0-5-S8  [R0805]  197.12 293.37 90 bottom
R161  NC/0-5-SA  [R1206]  202.71 293.37 90 bottom
R162  0-5-SA  [R1206]  205.76 293.37 90 bottom
R163  0-5-S8  [R0805]  194.58 293.37 90 bottom
R164  NC/0-5-S8  [R0805]  192.04 293.37 90 bottom
RB1  10K-1-S6  [R0603]  67.07 18.03 270 bottom
RB2  10K-1-S6  [R0603]  67.07 14.48 90 bottom
SB1  SHORT  [DEFAULT_SHORT_SMALL]  259.48 12.18 180 top
SB13  SHORT  [DEFAULT_SHORT_SMALL]  180.58 417.05 0 top
SB14  SHORT  [DEFAULT_SHORT_SMALL]  112.14 11.83 180 top
SB15  SHORT  [DEFAULT_SHORT_SMALL]  33.3 416.93 0 top
SCREW1  FY-V93KHSCREW  [PG_VG93K_F_HALFOUTLINE_FY]  146.32 214.63 0 top
SH3  SHORT  [DEFAULT_SHORT_SMALL]  184.92 204.99 0 bottom
SH4  SHORT  [DEFAULT_SHORT_SMALL]  184.95 203.8 0 bottom
SH5  SHORT  [DEFAULT_SHORT_SMALL]  162.4 212.67 0 bottom
SH6  SHORT  [DEFAULT_SHORT_SMALL]  162.45 211.68 0 bottom
SH7  SHORT  [DEFAULT_SHORT_SMALL]  149.14 198.58 270 bottom
SH8  SHORT  [DEFAULT_SHORT_SMALL]  148.13 198.62 270 bottom
SH9  SHORT  [DEFAULT_SHORT_SMALL]  131.12 212.67 180 bottom
SH10  SHORT  [DEFAULT_SHORT_SMALL]  131.11 213.51 180 bottom
SH11  SHORT  [DEFAULT_SHORT_SMALL]  145.14 232.5 90 bottom
SH12  SHORT  [DEFAULT_SHORT_SMALL]  146.01 232.5 90 bottom
SH13  SHORT  [DEFAULT_SHORT_SMALL]  139.86 232.51 90 bottom
SH14  SHORT  [DEFAULT_SHORT_SMALL]  140.94 232.5 90 bottom
SH15  SHORT  [DEFAULT_SHORT_SMALL]  161.99 218.29 0 bottom
SH16  SHORT  [DEFAULT_SHORT_SMALL]  162.03 219.18 0 bottom
SITE1  FSS0AS071A  [SK_BGA17X17_336P_0P8MM_S071AA]  146.32 214.63 0 top
TP_DPS11  TP01  [TP_040_T]  202.94 279.15 0 top
TP_DPS12  TP01  [TP_040_T]  172.46 279.15 0 top
TP_DPS13  TP01  [TP_040_T]  45.46 279.15 0 top
TP_DPS14  TP01  [TP_040_T]  147.06 279.15 0 top
TP_DPS21  TP01  [TP_040_T]  124.2 279.15 0 top
TP_DPS22  TP01  [TP_040_T]  96.26 279.15 0 top
TP_DPS23  TP01  [TP_040_T]  235.96 279.15 0 top
TR2  0-5-S4  [R0402_UNBGA_V2]  29.48 297.94 0 bottom
TR3  0-5-S4  [R0402_UNBGA_V2]  29.48 298.96 0 bottom
UB1  AT24C04C-SSHM-SO8  [SO8_215X127MM]  72.66 17.53 180 bottom
UHC230  UHC4A  [PG_VG93K_PF_UHC4_G8D230_A34_V2]  35.83 351.79 0 top
UHC430  UHC4B  [PG_VG93K_PF_UHC4_G8D430_B12_V2]  35.83 361.95 0 top
UNK038FY-S135BB14Q-A100  REF-CODE-PCB  [PCB_CODE]  231.41 210.57 0 top
UNK980FY-S071AA-1AH  REF-CODE-PCB  [PCB_CODE]  231.16 205.23 0 top
UT_UP5V1  TP03-D  [TP_060_040]  94 134.87 0 top
UTL1  V93K_UTL  [PG_VG93K_F_G3UTI1]  35.83 16.51 0 top
UTL2  V93K_UTL  [PG_VG93K_F_G1UTI2]  183.15 16.51 0 top
UTL3  V93K_UTL  [PG_VG93K_F_G2UTI3]  256.81 412.75 0 top
UTL4  V93K_UTL  [PG_VG93K_F_G8UTI4]  109.49 412.75 0 top
XC1  0.1U-50-X-S4-MU  [C0402]  72.66 21.08 180 bottom

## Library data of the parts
BDB4-BDB10 BDB13-BDB45 = BD120-3A-S8: User Part Number: PNXXXXXXXXXX; Tolerance: TOL
BGA289-12X12-P0.65 JG-250905AA011 = REF-CODE-SOCKET
C1 = 0.01U-16-X7R-S4-YA: User Part Number: PNXXXXXXXXXX; Tolerance: TOL
C2 = 3.3U-10-X-S4-TDK: User Part Number: PNXXXXXXXXXX; Tolerance: TOL
C3 C4 C50 C51 C56 C58 C62 C64 C68 C70 C74 C76 C81 C82 CB2 CB4 CB6 CB8 = 10U-25-X7R-SA: User Part Number: PNXXXXXXXXXX; Tolerance: TOL
C5 C8 C52 C55 C57 C61 C63 C67 C69 C73 C75 C79 C80 C85 = 22U-16-X-SB: User Part Number: PNXXXXXXXXXX; Tolerance: TOL
C6 C53 C59 C65 C71 C77 C83 = 47U-16-X5R-SB-MU: User Part Number: PNXXXXXXXXXX; Tolerance: TOL
C7 C54 C60 C66 C72 C78 C84 = 100U-10-X5R-SB-MU: User Part Number: PNXXXXXXXXXX; Tolerance: TOL
C9-C49 = 0.1U-16-X-S2-TDK: User Part Number: PNXXXXXXXXXX; Tolerance: TOL
CB1 CB3 CB5 CB7 = 0.1U-25-X-S6: User Part Number: PNXXXXXXXXXX; Tolerance: TOL
CSDPS225 CSDPS229 CSDPS425 CSDPS429 = V93K_CSDPS_DPS32: User Part Number: PNXXXXXXXXXX; Tolerance: TOL
CSDPS226 CSDPS426 = V93K_CSDPS_A: User Part Number: PNXXXXXXXXXX; Tolerance: TOL
D101-D124 D227 D228 D231 D232 D301-D324 D427 D428 D431 D432 = V93K_CH: Tolerance: TOL; User Part Number: PNXXXXXXXXXX
DPS1-DPS3 DPS8 = V93K_DPS: Tolerance: TOL; User Part Number: PNXXXXXXXXXX
FD1-FD16 TP_DPS11-TP_DPS14 TP_DPS21-TP_DPS23 = TP01: Tolerance: TOL; User Part Number: PNXXXXXXXXXX
FSS0AS071A = REF-CODE-CHIP
H1-H4 = M3-HOLE: Tolerance: TOL; User Part Number: PNXXXXXXXXXX
K1-K44 = 2911-05-321-A-V2: Tolerance: TOL; User Part Number: PNXXXXXXXXXX
K45 K46 = UA2-5NJ-A-V3: Tolerance: TOL; User Part Number: PNXXXXXXXXXX
KB1-2-KB1-4 KB1-6-KB1-8 KB2-2-KB2-4 KB2-6-KB2-8 KB3-4 KB3-5 KB3-8 KB4-4 KB4-5 KB4-8 UT_UP5V1 = TP03-D: Tolerance: TOL; User Part Number: PNXXXXXXXXXX
KS1 KS2 = 712D-5-V2: Tolerance: TOL; User Part Number: PNXXXXXXXXXX
KS3 KS4 = 2911-05-321-A: Tolerance: TOL; User Part Number: PNXXXXXXXXXX
LD1-LD46 = LDG-2-S6: Tolerance: TOL; User Part Number: PNXXXXXXXXXX
LDB1 = LDG-2-S8: User Part Number: PNXXXXXXXXXX; Tolerance: TOL
LDB2-LDB5 = LDG-2-S4: Tolerance: TOL; User Part Number: PNXXXXXXXXXX
LOGO1 = LOGO_KT_KSMT
LOGO2 = LOGO_FY_Faraday
LRB1 = 330-1-S6: User Part Number: PNXXXXXXXXXX; Tolerance: TOL
LRB2-LRB5 R1-R46 = 470-1-S4: User Part Number: PNXXXXXXXXXX; Tolerance: TOL
M5 = V93K-TOUCHSENSOR-FY: Tolerance: TOL; User Part Number: PNXXXXXXXXXX
OSC1 = OSC25M-S3225-AKER-3.3V: Tolerance: TOL; User Part Number: PNXXXXXXXXXX
R123 R124 R127-R130 R133-R136 R139-R142 R145-R148 R151-R154 R157-R160 R163 R164 = 0-5-S6: User Part Number: PNXXXXXXXXXX; Tolerance: TOL
R125 R126 R131 R132 R137 R138 R143 R144 R149 R150 R155 R156 R161 R162 = 0-5-SA: User Part Number: PNXXXXXXXXXX; Tolerance: TOL
RB1 RB2 = 10K-1-S6: User Part Number: PNXXXXXXXXXX; Tolerance: TOL
SB1 SB13-SB15 SH3-SH16 = SHORT: User Part Number: PNXXXXXXXXXX; Tolerance: TOL
SCREW1 = FY-V93KHSCREW: Tolerance: TOL; User Part Number: PNXXXXXXXXXX
SITE1 = FSS0AS071A: Tolerance: TOL; User Part Number: PNXXXXXXXXXX
TR2 TR3 = 0-5-S4: User Part Number: PNXXXXXXXXXX; Tolerance: TOL
UB1 = AT24C04C-SSHM-SO8: User Part Number: PNXXXXXXXXXX; Tolerance: TOL
UHC230 = UHC4A: User Part Number: PNXXXXXXXXXX; Tolerance: TOL
UHC430 = UHC4B: User Part Number: PNXXXXXXXXXX; Tolerance: TOL
UNK038FY-S135BB14Q-A100 UNK980FY-S071AA-1AH = REF-CODE-PCB
UTL1-UTL4 = V93K_UTL: User Part Number: PNXXXXXXXXXX; Tolerance: TOL
XC1 = 0.1U-50-X-S4-MU: User Part Number: PNXXXXXXXXXX; Tolerance: TOL

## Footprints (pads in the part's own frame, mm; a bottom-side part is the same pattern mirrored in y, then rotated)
C0201
  rect 0.305x0.356 smd: 1(-0.3,0) 2(0.3,0)
C0402
  custom 0.15x0.15 smd: 1(-0.5,0) 2(0.5,0)
C0603
  rect 0.889x0.889 smd: 1(-0.85,0) 2(0.85,0)
C1206
  rect 1.321x1.829 smd: 1(-1.25,0) 2(1.25,0)
C1210
  rect 1.27x3.048 smd: 1(-1.524,0) 2(1.524,0)
CHIP_CODE
  round 0.051 smd: 1(0,0)
DEFAULT_SHORT_SMALL
  custom 0.07x0.07 smd: 1(-0.5,0) 2(0.5,0)
FB0805
  rect 1.118x1.372 smd: 1(-0.965,0) 2(0.965,0)
FD_040_V2
  round 1.016 smd: 1(0,0)
LED_0603
  rect 0.8x0.8 smd: 1(0.749,0) 2(-0.749,0)
LED_0805
  rect 1.118x1.372 smd: 1(0.95,0) 2(-0.95,0)
